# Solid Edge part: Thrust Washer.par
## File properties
Title: Thrust Washer
Author: Dan
Template: Normal.par
Last saved by: Dan
Revision: 18
Application: Solid Edge
Material: steel
Density: 0 kg/mm^3
Accuracy: 0.99
Document Number: P52-004-3
Project Name: Piston Pump P52
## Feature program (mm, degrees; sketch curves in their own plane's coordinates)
sketch for "unnamed Protrusion 1" #1 plane through (0, 0, 0) normal (0, 0, 1) x-axis (1, 0, 0)
  circle centre (0, 0) radius 22.1
sketch for "unnamed Protrusion 1" #2 plane through (0, 0, 0) normal (0, 0, 1) x-axis (1, 0, 0)
  circle centre (0, 0) radius 41
extrude "unnamed Protrusion 1" add finite 4 symmetric
fillet "Round_1" radius 1
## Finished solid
Body 1: solid body, 8 faces, 8 edges, 0 vertices.
  Faces by surface: torus 4, cylinder 2, plane 2
  Edges by curve: circle 8
Bounding box of the edges (mm; curved faces can reach further): 82.000 x 82.000 x 4.000, from (-41, -41, -2) to (41, 41, 2).
Cylindrical faces by radius (mm): R22.1 x1, R41 x1
Toroidal faces (ring radius, tube radius in mm): R23.1 r1 x2, R40 r1 x2
Planar faces by outward normal: +z 1, -z 1
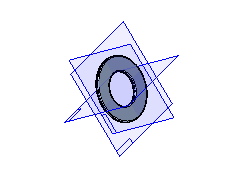
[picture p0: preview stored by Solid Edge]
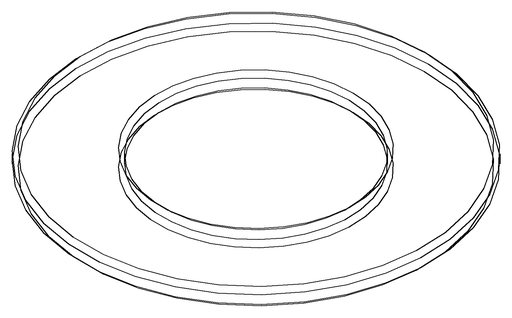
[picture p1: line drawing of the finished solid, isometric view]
